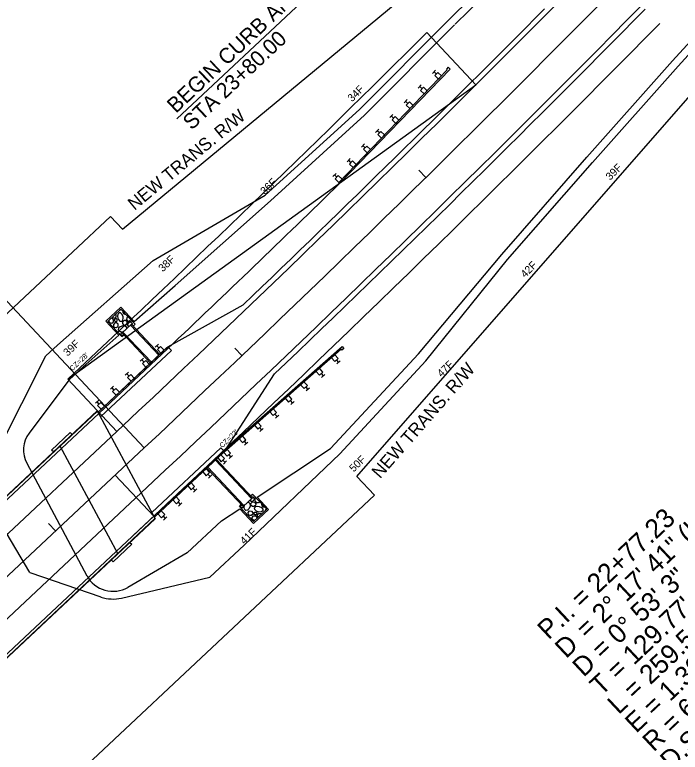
# Model space of a CAD drawing. Extents: x 1623239 to 1625698, y 1118659 to 1120751.
# Drawn here: x 1624416.9 to 1624676.8, y 1119574.5 to 1119862.6 of the extents above; entities that cross this region are included whole.
import ezdxf

# ---------------------------------------------------------------- set-up
doc = ezdxf.new("R2010")
doc.units = 0
for name, color, linetype in [('BR_CONCRETE', 7, 'Continuous'), ('BR_PROPOSED_TRAVELWAY', 7, 'Continuous'), ('Default', 7, 'Continuous'), ('Drainage-Trench', 7, 'Continuous'), ('RD_HC_CL_Rel', 7, 'Continuous'), ('RD_HC_Data', 7, 'Continuous'), ('RD_HC_Data_Tic', 7, 'Continuous'), ('RD_PD_BOC', 7, 'Continuous'), ('RD_PD_CstnLmt', 7, 'Continuous'), ('RD_PD_CstnLmt_TX', 7, 'Continuous'), ('RD_PD_DR_ErosCtrl', 7, 'Continuous'), ('RD_PD_Final_TrvlWay', 7, 'Continuous'), ('RD_PD_Final_TX', 7, 'Continuous'), ('RD_PD_GR', 7, 'Continuous'), ('RD_PD_PaveDit', 7, 'Continuous'), ('RD_PD_PaveShd', 7, 'Continuous'), ('RD_PD_RW', 7, 'Continuous'), ('RD_Sketch8', 7, 'Continuous')]:
    doc.layers.add(name, color=color, linetype=linetype)

# ---------------------------------------------------------------- blocks, each defined once
blk = doc.blocks.new('Guardrail_MTBBC3_Transition')
at = {"layer": 'RD_PD_GR'}
for p, q in [((3.525, 3.75), (1.775, 3.75)), ((2.65, 2.5), (2.65, 3.75)), ((11.525, 3.75), (9.775, 3.75)), ((10.65, 2.5), (10.65, 3.75)), ((19.525, 3.75), (17.775, 3.75)), ((18.65, 2.5), (18.65, 3.75)), ((27.525, 3.75), (25.775, 3.75)), ((26.65, 2.5), (26.65, 3.75)), ((35.525, 3.75), (33.775, 3.75)), ((34.65, 2.5), (34.65, 3.75)), ((37, 0.5), (0, 0.5)), ((0, 0.5), (0, 0)), ((0, 0), (37, 0)), ((1.775, 0.5), (1.775, 2.5)), ((1.775, 2.5), (3.525, 2.5)), ((3.525, 0.5), (1.775, 0.5)), ((3.525, 2.5), (3.525, 0.5)), ((9.775, 0.5), (9.775, 2.5)), ((9.775, 2.5), (11.525, 2.5)), ((11.525, 0.5), (9.775, 0.5)), ((11.525, 2.5), (11.525, 0.5)), ((17.775, 0.5), (17.775, 2.5)), ((17.775, 2.5), (19.525, 2.5)), ((19.525, 0.5), (17.775, 0.5)), ((19.525, 2.5), (19.525, 0.5)), ((25.775, 0.5), (25.775, 2.5)), ((25.775, 2.5), (27.525, 2.5)), ((27.525, 0.5), (25.775, 0.5)), ((27.525, 2.5), (27.525, 0.5)), ((30.65, 0.5), (30.65, 0)), ((33.775, 0.5), (33.775, 2.5)), ((33.775, 2.5), (35.525, 2.5)), ((35.525, 0.5), (33.775, 0.5)), ((35.525, 2.5), (35.525, 0.5)), ((37, 0), (37, 0.5))]:
    blk.add_line(p, q, dxfattribs=at)

msp = doc.modelspace()

# ---------------------------------------------------------------- linework, layer by layer
at = {"layer": 'BR_CONCRETE'}
for p, q in [((1624343.39, 1119608.68), (1624449.15, 1119707.87)), ((1624343.45, 1119608.57), (1624449.22, 1119707.76)), ((1624343.94, 1119607.65), (1624449.7, 1119706.85)), ((1624449.15, 1119707.87), (1624471.75, 1119665.66)), ((1624434.57, 1119694.19), (1624457.17, 1119651.98)), ((1624365.44, 1119567.5), (1624471.2, 1119666.69)), ((1624365.93, 1119566.58), (1624471.69, 1119665.77)), ((1624365.99, 1119566.47), (1624471.75, 1119665.66))]:
    msp.add_line(p, q, dxfattribs=at)
for points in [[(1624432.01, 1119691.8), (1624431.33, 1119692.53), (1624438.62, 1119699.37), (1624439.31, 1119698.64)], [(1624455.3, 1119648.85), (1624454.61, 1119649.58), (1624461.91, 1119656.42), (1624462.59, 1119655.69)]]:
    msp.add_lwpolyline(points, close=True, dxfattribs=at)
at = {"layer": 'BR_PROPOSED_TRAVELWAY'}
for p, q in [((1624348.83, 1119598.53), (1624454.59, 1119697.72)), ((1624360.55, 1119576.62), (1624466.32, 1119675.81))]:
    msp.add_line(p, q, dxfattribs=at)
at = {"layer": 'Default'}
msp.add_line((1624365.44, 1119567.5), (1624471.2, 1119666.69), dxfattribs=at)
at = {"layer": 'Drainage-Trench'}
for p, q in [((1624453.22, 1119742.79), (1624458.32, 1119747.58)), ((1624463.88, 1119741.65), (1624458.32, 1119747.58)), ((1624458.77, 1119736.86), (1624453.22, 1119742.79)), ((1624458.82, 1119738.28), (1624462.47, 1119741.7)), ((1624462.1, 1119741.36), (1624473.18, 1119729.54)), ((1624462.47, 1119741.7), (1624473.54, 1119729.89)), ((1624463.15, 1119740.97), (1624463.88, 1119741.65)), ((1624458.82, 1119738.28), (1624469.9, 1119726.47)), ((1624459.18, 1119738.62), (1624470.26, 1119726.81)), ((1624458.77, 1119736.86), (1624459.5, 1119737.55)), ((1624509.73, 1119673.87), (1624495.63, 1119688.91)), ((1624506.45, 1119670.79), (1624492.35, 1119685.83)), ((1624509.36, 1119673.53), (1624495.26, 1119688.56)), ((1624506.08, 1119670.45), (1624491.98, 1119685.49)), ((1624509.05, 1119674.6), (1624509.77, 1119675.28)), ((1624509.77, 1119675.28), (1624515.33, 1119669.36)), ((1624506.08, 1119670.45), (1624509.73, 1119673.87)), ((1624504.67, 1119670.5), (1624505.4, 1119671.18)), ((1624504.67, 1119670.5), (1624510.22, 1119664.57)), ((1624510.22, 1119664.57), (1624515.33, 1119669.36))]:
    msp.add_line(p, q, dxfattribs=at)
at = {"layer": 'RD_HC_CL_Rel'}
msp.add_line((1624334.12, 1119568.29), (1624467.48, 1119693.35), dxfattribs=at)
msp.add_arc((1620034.69, 1124419.96), 6480, 313.16267, 315.457254, dxfattribs=at)
at = {"layer": 'RD_HC_Data'}
msp.add_line((1624467.48, 1119693.35), (1624367.16, 1119800.32), dxfattribs=at)
at = {"layer": 'RD_HC_Data_Tic'}
for p, q in [((1624577.5, 1119799), (1624574.7, 1119801.85)), ((1624505.66, 1119729.45), (1624502.9, 1119732.34)), ((1624432.86, 1119660.89), (1624430.12, 1119663.8))]:
    msp.add_line(p, q, dxfattribs=at)
at = {"layer": 'RD_PD_BOC'}
for p, q in [((1624449.36, 1119707.21), (1624476.75, 1119732.89)), ((1624476.75, 1119732.89), (1624478.11, 1119731.43)), ((1624478.11, 1119731.43), (1624450.44, 1119705.48)), ((1624497.46, 1119693.37), (1624470.47, 1119668.06)), ((1624471.45, 1119666.23), (1624498.83, 1119691.91)), ((1624498.83, 1119691.91), (1624497.46, 1119693.37))]:
    msp.add_line(p, q, dxfattribs=at)
at = {"layer": 'RD_PD_CstnLmt'}
for p, q in [((1624588.92, 1119858.88), (1624612.6, 1119882.23)), ((1624673.75, 1119844.52), (1624707.3, 1119881.4)), ((1624553.56, 1119823.35), (1624588.65, 1119858.61)), ((1624640.29, 1119806.89), (1624673.75, 1119844.52)), ((1624516.75, 1119789.87), (1624553.56, 1119823.35)), ((1624607.1, 1119768.89), (1624640.29, 1119806.89)), ((1624479.55, 1119756.84), (1624516.75, 1119789.87)), ((1624574.57, 1119730.15), (1624607.1, 1119768.89)), ((1624463.59, 1119742.69), (1624479.55, 1119756.84)), ((1624452.51, 1119742.81), (1624458.35, 1119748.28)), ((1624458.35, 1119748.28), (1624463.59, 1119742.69)), ((1624457.6, 1119737.39), (1624452.51, 1119742.81)), ((1624442.33, 1119723.86), (1624457.6, 1119737.39)), ((1624540.28, 1119693.12), (1624574.57, 1119730.15)), ((1624442.33, 1119723.86), (1624437.99, 1119719.78)), ((1624437.99, 1119719.78), (1624422.52, 1119699.13)), ((1624511.58, 1119674.09), (1624540.28, 1119693.12)), ((1624421.62, 1119687.33), (1624445.13, 1119643.41)), ((1624516.04, 1119669.34), (1624511.58, 1119674.09)), ((1624497.68, 1119664.88), (1624504.81, 1119669.61)), ((1624504.81, 1119669.61), (1624510.2, 1119663.87)), ((1624510.2, 1119663.87), (1624516.04, 1119669.34)), ((1624497.68, 1119664.88), (1624484.27, 1119652.31)), ((1624484.27, 1119652.31), (1624461.07, 1119638.88))]:
    msp.add_line(p, q, dxfattribs=at)
for centre, radius, start, end in [((1624431.33, 1119692.53), 11.01, 143.1621, 208.1627), ((1624455.3, 1119648.85), 11.53, 208.1627, 300.0691)]:
    msp.add_arc(centre, radius, start, end, dxfattribs=at)
at = {"layer": 'RD_PD_DR_ErosCtrl'}
for p, q in [((1624586.54, 1119860.74), (1624612.56, 1119886.58)), ((1624675.98, 1119842.52), (1624709.49, 1119879.36)), ((1624551.44, 1119825.47), (1624586.54, 1119860.74)), ((1624642.54, 1119804.9), (1624675.98, 1119842.52)), ((1624514.76, 1119792.12), (1624551.54, 1119825.57)), ((1624609.39, 1119766.95), (1624642.54, 1119804.9)), ((1624470.93, 1119766.57), (1624514.76, 1119792.12)), ((1624433.57, 1119733.46), (1624470.93, 1119766.57)), ((1624577.5, 1119727.43), (1624609.39, 1119766.95)), ((1624429.09, 1119729.26), (1624433.57, 1119733.46)), ((1624410.22, 1119692.05), (1624429.09, 1119729.26)), ((1624543.85, 1119691.09), (1624577.5, 1119727.43)), ((1624506.58, 1119655.4), (1624543.85, 1119691.09)), ((1624422.77, 1119644.63), (1624408.1, 1119669.48)), ((1624493.17, 1119642.83), (1624506.58, 1119655.4)), ((1624422.77, 1119644.63), (1624450.59, 1119635.11)), ((1624458.62, 1119634.71), (1624493.17, 1119642.83))]:
    msp.add_line(p, q, dxfattribs=at)
msp.add_arc((1624455.3, 1119648.85), 14.53, 251.1042, 283.2212, dxfattribs=at)
at = {"layer": 'RD_PD_Final_TrvlWay'}
for p, q in [((1624454.59, 1119697.72), (1624459.27, 1119702.11)), ((1624466.32, 1119675.81), (1624475.69, 1119684.6))]:
    msp.add_line(p, q, dxfattribs=at)
for radius in [6468, 6492]:
    msp.add_arc((1620034.69, 1124419.96), radius, 313.16267, 315.457254, dxfattribs=at)
at = {"layer": 'RD_PD_Final_TX'}
msp.add_line((1624480.25, 1119821.93), (1624568.08, 1119904.3), dxfattribs=at)
at = {"layer": 'RD_PD_GR'}
for p, q in [((1624586.2, 1119842.06), (1624585.5, 1119841.34)), ((1624586.92, 1119841.37), (1624586.2, 1119842.06)), ((1624585.86, 1119841), (1624543.52, 1119797.09)), ((1624543.88, 1119796.74), (1624586.92, 1119841.37)), ((1624581.27, 1119840.91), (1624580.05, 1119839.65)), ((1624581.56, 1119839.42), (1624580.66, 1119840.28)), ((1624580.95, 1119838.79), (1624582.17, 1119840.05)), ((1624582.39, 1119837.4), (1624580.95, 1119838.79)), ((1624582.17, 1119840.05), (1624583.61, 1119838.66)), ((1624583.61, 1119838.66), (1624582.39, 1119837.4)), ((1624585.5, 1119841.34), (1624585.86, 1119841)), ((1624575.71, 1119835.16), (1624574.5, 1119833.9)), ((1624576.01, 1119833.66), (1624575.11, 1119834.53)), ((1624575.4, 1119833.03), (1624576.61, 1119834.29)), ((1624576.84, 1119831.64), (1624575.4, 1119833.03)), ((1624576.61, 1119834.29), (1624578.05, 1119832.9)), ((1624578.05, 1119832.9), (1624576.84, 1119831.64)), ((1624570.16, 1119829.4), (1624568.95, 1119828.14)), ((1624570.45, 1119827.9), (1624569.55, 1119828.77)), ((1624569.84, 1119827.27), (1624571.06, 1119828.53)), ((1624571.28, 1119825.88), (1624569.84, 1119827.27)), ((1624571.06, 1119828.53), (1624572.5, 1119827.14)), ((1624572.5, 1119827.14), (1624571.28, 1119825.88)), ((1624564.61, 1119823.64), (1624563.39, 1119822.38)), ((1624564.9, 1119822.14), (1624564, 1119823.01)), ((1624564.29, 1119821.51), (1624565.51, 1119822.77)), ((1624565.73, 1119820.12), (1624564.29, 1119821.51)), ((1624565.51, 1119822.77), (1624566.95, 1119821.38)), ((1624566.95, 1119821.38), (1624565.73, 1119820.12)), ((1624559.05, 1119817.88), (1624557.84, 1119816.62)), ((1624559.35, 1119816.38), (1624558.45, 1119817.25)), ((1624558.74, 1119815.75), (1624559.95, 1119817.01)), ((1624560.18, 1119814.37), (1624558.74, 1119815.75)), ((1624559.95, 1119817.01), (1624561.39, 1119815.62)), ((1624561.39, 1119815.62), (1624560.18, 1119814.37)), ((1624553.5, 1119812.12), (1624552.28, 1119810.86)), ((1624553.79, 1119810.62), (1624552.89, 1119811.49)), ((1624553.18, 1119810), (1624554.4, 1119811.25)), ((1624554.62, 1119808.61), (1624553.18, 1119810)), ((1624554.4, 1119811.25), (1624555.84, 1119809.87)), ((1624555.84, 1119809.87), (1624554.62, 1119808.61)), ((1624547.95, 1119806.36), (1624546.73, 1119805.1)), ((1624548.24, 1119804.87), (1624547.34, 1119805.73)), ((1624547.63, 1119804.24), (1624548.85, 1119805.5)), ((1624549.07, 1119802.85), (1624547.63, 1119804.24)), ((1624548.85, 1119805.5), (1624550.28, 1119804.11)), ((1624550.28, 1119804.11), (1624549.07, 1119802.85)), ((1624542.39, 1119800.61), (1624541.18, 1119799.35)), ((1624542.68, 1119799.11), (1624541.78, 1119799.98)), ((1624542.08, 1119798.48), (1624543.29, 1119799.74)), ((1624543.52, 1119797.09), (1624542.08, 1119798.48)), ((1624543.29, 1119799.74), (1624544.73, 1119798.35)), ((1624544.73, 1119798.35), (1624543.52, 1119797.09)), ((1624543.52, 1119797.09), (1624543.88, 1119796.74)), ((1624498.19, 1119692), (1624544.76, 1119732.93)), ((1624545.42, 1119732.18), (1624544.67, 1119731.52)), ((1624544.76, 1119732.93), (1624545.42, 1119732.18)), ((1624544.34, 1119731.89), (1624498.52, 1119691.62)), ((1624541.9, 1119729.75), (1624540.58, 1119728.59)), ((1624543.22, 1119728.25), (1624541.9, 1119729.75)), ((1624544.67, 1119731.52), (1624544.34, 1119731.89)), ((1624540.58, 1119728.59), (1624541.9, 1119727.09)), ((1624541.9, 1119727.09), (1624543.22, 1119728.25)), ((1624542.56, 1119727.67), (1624543.39, 1119726.73)), ((1624544.04, 1119727.31), (1624542.73, 1119726.15)), ((1624535.89, 1119724.47), (1624534.57, 1119723.31)), ((1624534.57, 1119723.31), (1624535.9, 1119721.81)), ((1624537.21, 1119722.96), (1624535.89, 1119724.47)), ((1624535.9, 1119721.81), (1624537.21, 1119722.96)), ((1624536.55, 1119722.39), (1624537.38, 1119721.45)), ((1624538.03, 1119722.03), (1624536.72, 1119720.87)), ((1624529.88, 1119719.18), (1624528.57, 1119718.03)), ((1624528.57, 1119718.03), (1624529.89, 1119716.53)), ((1624531.2, 1119717.68), (1624529.88, 1119719.18)), ((1624529.89, 1119716.53), (1624531.2, 1119717.68)), ((1624530.54, 1119717.1), (1624531.37, 1119716.17)), ((1624532.03, 1119716.74), (1624530.71, 1119715.59)), ((1624523.87, 1119713.9), (1624522.56, 1119712.75)), ((1624522.56, 1119712.75), (1624523.88, 1119711.25)), ((1624525.19, 1119712.4), (1624523.87, 1119713.9)), ((1624523.88, 1119711.25), (1624525.19, 1119712.4)), ((1624524.54, 1119711.82), (1624525.36, 1119710.88)), ((1624526.02, 1119711.46), (1624524.7, 1119710.31)), ((1624517.86, 1119708.62), (1624516.55, 1119707.47)), ((1624516.55, 1119707.47), (1624517.87, 1119705.96)), ((1624519.18, 1119707.12), (1624517.86, 1119708.62)), ((1624517.87, 1119705.96), (1624519.18, 1119707.12)), ((1624518.53, 1119706.54), (1624519.35, 1119705.6)), ((1624520.01, 1119706.18), (1624518.69, 1119705.02)), ((1624511.85, 1119703.34), (1624510.54, 1119702.18)), ((1624513.17, 1119701.84), (1624511.85, 1119703.34)), ((1624510.54, 1119702.18), (1624511.86, 1119700.68)), ((1624511.86, 1119700.68), (1624513.17, 1119701.84)), ((1624512.52, 1119701.26), (1624513.34, 1119700.32)), ((1624514, 1119700.9), (1624512.69, 1119699.74)), ((1624505.85, 1119698.06), (1624504.53, 1119696.9)), ((1624507.17, 1119696.56), (1624505.85, 1119698.06)), ((1624504.53, 1119696.9), (1624505.85, 1119695.4)), ((1624505.85, 1119695.4), (1624507.17, 1119696.56)), ((1624506.51, 1119695.98), (1624507.33, 1119695.04)), ((1624507.99, 1119695.62), (1624506.68, 1119694.46)), ((1624498.52, 1119691.62), (1624498.19, 1119692)), ((1624499.84, 1119692.78), (1624498.52, 1119691.62)), ((1624498.52, 1119691.62), (1624499.84, 1119690.12)), ((1624501.16, 1119691.27), (1624499.84, 1119692.78)), ((1624499.84, 1119690.12), (1624501.16, 1119691.27)), ((1624500.5, 1119690.7), (1624501.33, 1119689.76)), ((1624501.98, 1119690.34), (1624500.67, 1119689.18))]:
    msp.add_line(p, q, dxfattribs=at)
msp.add_arc((1620034.75, 1124419.9), 6458, 313.457809, 314.284639, dxfattribs=at)
at = {"layer": 'RD_PD_PaveDit'}
for p, q in [((1624459.46, 1119745.7), (1624460.24, 1119745.53)), ((1624461.35, 1119740.73), (1624461.42, 1119740.72)), ((1624462.32, 1119742.81), (1624462.66, 1119742.95)), ((1624459.11, 1119738.75), (1624459.48, 1119738.9)), ((1624508.69, 1119672.82), (1624508.68, 1119672.89)), ((1624510.83, 1119673.66), (1624510.99, 1119673.99)), ((1624513.53, 1119670.61), (1624513.41, 1119671.4)), ((1624506.57, 1119670.71), (1624506.75, 1119671.07))]:
    msp.add_line(p, q, dxfattribs=at)
for points in [[(1624457.88, 1119747.16), (1624458.18, 1119747.28), (1624458.39, 1119747.51)], [(1624459.14, 1119746.7), (1624459.12, 1119746.23), (1624459.46, 1119745.7)], [(1624453.96, 1119742.29), (1624454.82, 1119742.11), (1624455.44, 1119742.62), (1624455.45, 1119743.43), (1624454.84, 1119743.97), (1624454.45, 1119743.95)], [(1624454.94, 1119744.4), (1624455.03, 1119744.26)], [(1624455.03, 1119744.26), (1624455.89, 1119744.08), (1624456.51, 1119744.6), (1624456.52, 1119745.41), (1624456.26, 1119745.64)], [(1624456.03, 1119742.82), (1624456.54, 1119742.72), (1624456.92, 1119743.03), (1624456.92, 1119743.51), (1624456.55, 1119743.83), (1624456.17, 1119743.81), (1624455.84, 1119743.46), (1624455.83, 1119743.15), (1624456.03, 1119742.82)], [(1624459.28, 1119744.56), (1624458.91, 1119745.5), (1624458.26, 1119746.08), (1624457.7, 1119746.11), (1624457.19, 1119745.62), (1624457.04, 1119744.62), (1624457.35, 1119743.59), (1624457.96, 1119742.91), (1624458.57, 1119742.79), (1624459.14, 1119743.25), (1624459.32, 1119743.99), (1624459.28, 1119744.6)], [(1624461.15, 1119744.57), (1624460.68, 1119744.14), (1624460.55, 1119743.53), (1624461.01, 1119742.96), (1624461.76, 1119742.77), (1624462.37, 1119742.82)], [(1624453.64, 1119743.18), (1624453.63, 1119742.82), (1624453.96, 1119742.29)], [(1624455.77, 1119740.57), (1624456.63, 1119740.39), (1624457.25, 1119740.9), (1624457.26, 1119741.71), (1624456.64, 1119742.25), (1624456, 1119742.21), (1624455.46, 1119741.62), (1624455.43, 1119741.1), (1624455.77, 1119740.57)], [(1624460.65, 1119739.99), (1624460.67, 1119740.34), (1624460.17, 1119740.84), (1624459.17, 1119741), (1624458.14, 1119740.69), (1624457.46, 1119740.08), (1624457.34, 1119739.46), (1624457.8, 1119738.9), (1624458.55, 1119738.71), (1624459.15, 1119738.76)], [(1624459.36, 1119741.46), (1624460.22, 1119741.29), (1624460.84, 1119741.8), (1624460.85, 1119742.61), (1624460.23, 1119743.15), (1624459.59, 1119743.11), (1624459.05, 1119742.52), (1624459.02, 1119742), (1624459.36, 1119741.47)], [(1624462.83, 1119741.31), (1624462.84, 1119741.87), (1624462.22, 1119742.41), (1624461.58, 1119742.37), (1624461.04, 1119741.79), (1624461.01, 1119741.27), (1624461.35, 1119740.73)], [(1624459.02, 1119738.46), (1624458.67, 1119738.44), (1624458.35, 1119738.09), (1624458.33, 1119737.78), (1624458.53, 1119737.46)], [(1624458.53, 1119737.46), (1624459.05, 1119737.35), (1624459.41, 1119737.65)], [(1624507.91, 1119672.16), (1624508.26, 1119672.16), (1624508.73, 1119671.64), (1624508.82, 1119670.63), (1624508.45, 1119669.62), (1624507.79, 1119668.98), (1624507.17, 1119668.9), (1624506.64, 1119669.39), (1624506.5, 1119670.15), (1624506.59, 1119670.75)], [(1624509.36, 1119674.26), (1624509.93, 1119674.23), (1624510.43, 1119673.58), (1624510.35, 1119672.94), (1624509.73, 1119672.44), (1624509.21, 1119672.45), (1624508.69, 1119672.82)], [(1624509.3, 1119670.79), (1624509.17, 1119671.66), (1624509.73, 1119672.24), (1624510.54, 1119672.2), (1624511.03, 1119671.55), (1624510.95, 1119670.91), (1624510.33, 1119670.41), (1624509.81, 1119670.42), (1624509.3, 1119670.79)], [(1624512.51, 1119672.37), (1624512.05, 1119671.93), (1624511.43, 1119671.85), (1624510.9, 1119672.34), (1624510.76, 1119673.1), (1624510.85, 1119673.7)], [(1624505.24, 1119670.22), (1624505.17, 1119670.74), (1624505.49, 1119671.08)], [(1624506.28, 1119670.64), (1624506.24, 1119670.29), (1624505.87, 1119669.99), (1624505.55, 1119670), (1624505.24, 1119670.22)], [(1624508.17, 1119667.26), (1624508.05, 1119668.13), (1624508.6, 1119668.71), (1624509.41, 1119668.67), (1624509.9, 1119668.03), (1624509.83, 1119667.38), (1624509.21, 1119666.88), (1624508.68, 1119666.89), (1624508.17, 1119667.26)], [(1624512.38, 1119670.51), (1624513.29, 1119670.08), (1624513.83, 1119669.4), (1624513.83, 1119668.83), (1624513.31, 1119668.36), (1624512.3, 1119668.27), (1624511.28, 1119668.64), (1624510.65, 1119669.3), (1624510.56, 1119669.92), (1624511.06, 1119670.45), (1624511.82, 1119670.59), (1624512.42, 1119670.5)], [(1624514.51, 1119670.23), (1624514.04, 1119670.24), (1624513.53, 1119670.61)], [(1624514.89, 1119668.95), (1624515.02, 1119669.23), (1624515.27, 1119669.43)], [(1624509.77, 1119665.35), (1624509.65, 1119666.22), (1624510.2, 1119666.8), (1624511.01, 1119666.76), (1624511.51, 1119666.11), (1624511.46, 1119665.73)], [(1624510.44, 1119667.38), (1624510.37, 1119667.9), (1624510.7, 1119668.25), (1624511.18, 1119668.22), (1624511.48, 1119667.83), (1624511.43, 1119667.45), (1624511.06, 1119667.15), (1624510.75, 1119667.15), (1624510.44, 1119667.38)], [(1624511.81, 1119666.29), (1624511.69, 1119667.16), (1624512.24, 1119667.74), (1624513.05, 1119667.7), (1624513.26, 1119667.42)], [(1624511.95, 1119666.19), (1624511.81, 1119666.29)], [(1624510.65, 1119664.97), (1624510.29, 1119664.98), (1624509.77, 1119665.35)]]:
    msp.add_lwpolyline(points, dxfattribs=at)
at = {"layer": 'RD_PD_PaveShd'}
for p, q in [((1624476.75, 1119732.89), (1624506.13, 1119749.26)), ((1624498.83, 1119691.91), (1624518.37, 1119722.23))]:
    msp.add_line(p, q, dxfattribs=at)
for radius, start, end in [(6466, 313.75143, 315.213737), (6494, 313.664525, 315.457254)]:
    msp.add_arc((1620034.69, 1124419.96), radius, start, end, dxfattribs=at)
at = {"layer": 'RD_PD_RW'}
for p, q in [((1624458.96, 1119778.79), (1624670.67, 1119953.92)), ((1624550.56, 1119682.16), (1624683.49, 1119834.14)), ((1624236, 1119579.09), (1624454.27, 1119783.79)), ((1624458.96, 1119778.79), (1624454.27, 1119783.79)), ((1624550.56, 1119682.16), (1624557.4, 1119674.87)), ((1624338, 1119469.11), (1624557.4, 1119674.87))]:
    msp.add_line(p, q, dxfattribs=at)
at = {"layer": 'RD_Sketch8'}
for p, q in [((1624597.05, 1119835.21), (1624577.89, 1119855.65)), ((1624437.6, 1119720.17), (1624597.05, 1119835.21)), ((1624437.6, 1119720.17), (1624440.11, 1119722.53)), ((1624456.76, 1119699.75), (1624437.6, 1119720.17)), ((1624471.2, 1119666.69), (1624456.15, 1119682.73)), ((1624463.12, 1119659.11), (1624482.53, 1119677.31))]:
    msp.add_line(p, q, dxfattribs=at)
for radius, end in [(6502, 315.457254), (6440, 314.867171)]:
    msp.add_arc((1620034.69, 1124419.96), radius, 313.16267, end, dxfattribs=at)

# ---------------------------------------------------------------- block references
at = {"layer": 'RD_PD_Final_TrvlWay', "rotation": 43.16266984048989}
msp.add_blockref('Guardrail_MTBBC3_Transition', (1624449.7, 1119706.85), dxfattribs=at)
at = {"layer": 'RD_PD_Final_TrvlWay', "yscale": -1, "rotation": 43.16266984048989}
msp.add_blockref('Guardrail_MTBBC3_Transition', (1624471.2, 1119666.69), dxfattribs=at)

# ---------------------------------------------------------------- texts
at = {"layer": 'RD_HC_Data'}
for s, p in [('    = 2%%d 17\' 41" (LT)', (1624632.25, 1119610.81)), ('P.I. = 22+77.23', (1624625.41, 1119618.11)), ('D = 0%%d 53\' 3"', (1624639.09, 1119603.52)), ("T = 129.77'", (1624645.93, 1119596.22)), ("L = 259.51'", (1624652.77, 1119588.93)), ('D', (1624632.25, 1119610.81)), ("R = 6,480.00'", (1624666.45, 1119574.34)), ('D.S. = 45 MPH', (1624673.29, 1119567.05)), ("E = 1.30'", (1624659.61, 1119581.64))]:
    msp.add_text(s, height=7.5, rotation=43.1627, dxfattribs=at).set_placement(p)
at = {"layer": 'RD_PD_CstnLmt_TX'}
for s, rotation, p in [('34F', 44.5114, (1624548.66, 1119828.35)), ('39F', 44.9535, (1624649.47, 1119797.69)), ('36F', 44.0693, (1624514.56, 1119792.06)), ('38F', 43.6272, (1624474.72, 1119761.91)), ('42F', 44.5114, (1624616.22, 1119759.62)), ('39F', 43.1851, (1624437.54, 1119728.96)), ('47F', 44.0693, (1624583.61, 1119720.81)), ('50F', 43.6272, (1624549.25, 1119683.71)), ('41F', 43.1851, (1624506.58, 1119655.4))]:
    msp.add_text(s, height=3, rotation=rotation, dxfattribs=at).set_placement(p)
at = {"layer": 'RD_PD_Final_TX'}
for s, p in [('BEGIN CURB AND GUTTER', (1624479.85, 1119823.82)), ('STA 23+80.00', (1624486.01, 1119817.25))]:
    msp.add_text(s, height=6, rotation=43.1625, dxfattribs=at).set_placement(p)
at = {"layer": 'RD_PD_RW'}
for rotation, p in [(39.5981, (1624463.67, 1119785.93)), (48.8268, (1624559.59, 1119681.09))]:
    msp.add_text('NEW TRANS. R/W', height=5, rotation=rotation, dxfattribs=at).set_placement(p)
at = {"layer": 'RD_Sketch8'}
for s, rotation, p in [("CZ=28'", 43.1627, (1624439.43, 1119723.26)), ("CZ=22'", 43.3577, (1624497.96, 1119693.2))]:
    msp.add_text(s, height=2, rotation=rotation, dxfattribs=at).set_placement(p)

doc.saveas('drawing.dxf')
